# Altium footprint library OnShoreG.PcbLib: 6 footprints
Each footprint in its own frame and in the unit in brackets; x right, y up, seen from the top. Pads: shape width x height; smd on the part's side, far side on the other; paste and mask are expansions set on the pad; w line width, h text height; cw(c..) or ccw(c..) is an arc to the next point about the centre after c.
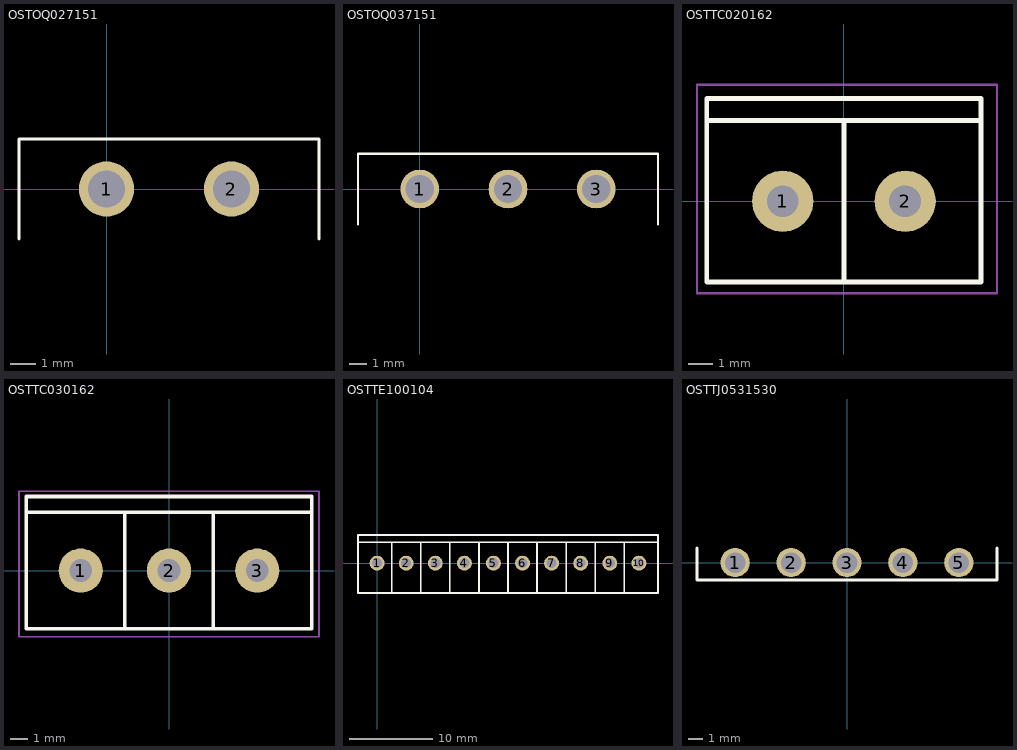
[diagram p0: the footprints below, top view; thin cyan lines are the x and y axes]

## OSTOQ027151 [mm] "Terminal Block Header 5mm"
height 8.5
pads (2):
  round 2.2 hole 1.5: 1(0,0) 2(5,0)
Top Overlay:
  lines w0.127: -3.5,-2 -3.5,2 8.5,2 8.5,-2
3D body: height 8.5, standoff -4, extent -3.5,-10 8.5,2

## OSTOQ037151 [mm] "Terminal Block Header 5mm"
height 8.5
pads (3):
  round 2.2 hole 1.6: 1(0,0) 2(5,0) 3(10,0)
Top Overlay:
  lines w0.127: -3.5,-2 -3.5,2 13.5,2 13.5,-2
3D body: height 8.5, standoff -4, extent -3.5,-10 13.5,2

## OSTTC020162 [mm]
height 9.9
pads (2):
  round 2.5 hole 1.3: 1(-2.5,0) 2(2.5,0)
Top Overlay:
  lines w0.2: -5.6,3.3 5.6,3.3 ; 0,-3.3 0,3.3 ; -5.6,-3.3 -5.6,4.2 5.6,4.2 5.6,-3.3 -5.6,-3.3
Mechanical 15:
  lines w0.1: -6,-3.75 -6,4.75 6.25,4.75 6.25,-3.75 -6,-3.75

## OSTTC030162 [mm]
height 9.9
pads (3):
  round 2.5 hole 1.3: 1(-5,0) 2(0,0) 3(5,0)
Top Overlay:
  lines w0.2: -8.1,3.3 8.1,3.3 ; -2.5,-3.3 -2.5,3.3 ; 2.5,-3.3 2.5,3.3 ; -8.1,-3.3 8.1,-3.3 8.1,4.2 -8.1,4.2 -8.1,-3.3
Mechanical 15:
  lines w0.1: -8.5,-3.75 8.5,-3.75 8.5,4.5 -8.5,4.5 -8.5,-3.75

## OSTTE100104 [mm]
height 8.4
pads (10):
  round 1.8 hole 1.2: 1(0,0) 2(3.5,0) 3(7,0) 4(10.5,0) 5(14,0) 6(17.5,0) 7(21,0) 8(24.5,0) 9(28,0) 10(31.5,0)
Top Overlay:
  lines w0.203: -2.3,2.5 33.7,2.5 ; 1.75,-3.6 1.75,2.5 ; 5.25,-3.6 5.25,2.5 ; 8.75,-3.6 8.75,2.5 ; 12.25,-3.6 12.25,2.5 ; 15.75,-3.6 15.75,2.5 ; 19.25,-3.6 19.25,2.5 ; 22.75,-3.6 22.75,2.5 ; 26.25,-3.6 26.25,2.5 ; 29.75,-3.6 29.75,2.5 ; -2.3,-3.6 33.8,-3.6 33.8,3.4 -2.3,3.4 -2.3,-3.6
3D body: height 8.4, standoff 0, extent -2.3,-3.6 33.8,3.4

## OSTTJ0531530 [mm]
height 7
pads (5):
  round 2 hole 1.4: 1(-7.62,0) 2(-3.81,0) 3(0,0) 4(3.81,0) 5(7.62,0)
Top Overlay:
  lines w0.203: -10.22,1 -10.22,-1.2 10.22,-1.2 10.22,1
3D body: height 7, standoff 0, extent -10.22,-1.2 10.22,8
